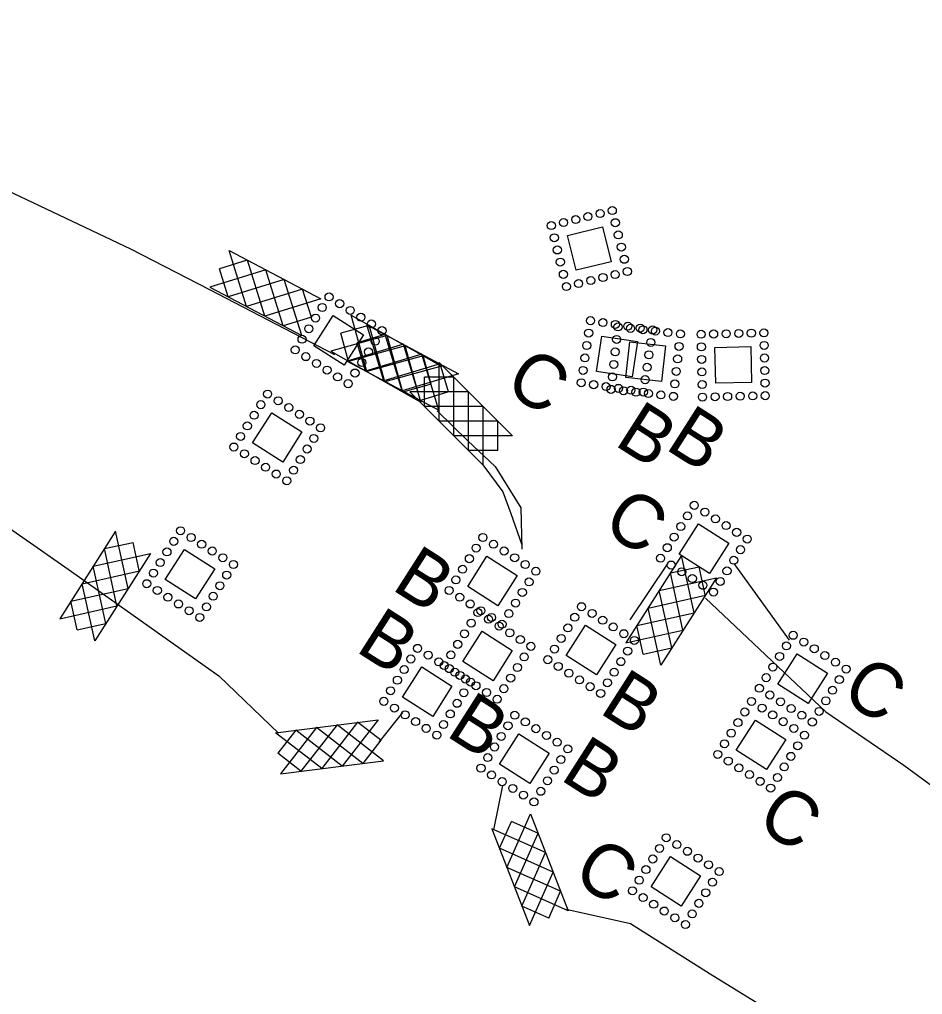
# Model space of a CAD drawing. Extents: x 2023536 to 2025544, y 819438 to 821266.
# Drawn here: x 2024579.5 to 2024831.1, y 820383.6 to 820655.3 of the extents above; entities that cross this region are included whole.
import ezdxf

# ---------------------------------------------------------------- set-up
doc = ezdxf.new("R2010")
doc.units = 0
for name, color, linetype in [('Label B Both CELL', 7, 'Continuous'), ('Label B CG CELL', 7, 'Continuous'), ('Label C Both CELL', 7, 'Continuous'), ('Label C Final CELL', 7, 'Continuous'), ('Rock Inlet Sediment Trap Type B Both CELL', 7, 'Continuous'), ('Rock Inlet Sediment Trap Type B CG CELL', 7, 'Continuous'), ('Rock Inlet Sediment Trap Type C Both CELL', 7, 'Continuous'), ('Rock Inlet Sediment Trap Type C Final CELL', 7, 'Continuous'), ('Rock Silt Check Type A Both CELL', 7, 'Continuous'), ('Rock Silt Check Type A CG CELL', 7, 'Continuous'), ('Rock Silt Check Type A Final CELL', 7, 'Continuous'), ('Temporary Silt Fence Both', 7, 'Continuous'), ('Temporary Silt Fence CG', 7, 'Continuous'), ('Temporary Silt Fence Final', 7, 'Continuous')]:
    doc.layers.add(name, color=color, linetype=linetype)

msp = doc.modelspace()

# ---------------------------------------------------------------- linework, layer by layer
at = {"layer": 'Rock Inlet Sediment Trap Type B Both CELL'}
for points in [[(2024749.55, 820565.48), (2024759.49, 820564.36), (2024758.37, 820554.43), (2024748.44, 820555.55)], [(2024773.22, 820563.91), (2024783.22, 820564.14), (2024783.45, 820554.14), (2024773.45, 820553.93)]]:
    msp.add_lwpolyline(points, close=True, dxfattribs=at)
for centre in [(2024746.24, 820569.63), (2024749.72, 820569.24), (2024753.19, 820568.85), (2024745.85, 820566.15), (2024756.67, 820568.46), (2024760.15, 820568.07), (2024763.63, 820567.68), (2024769.38, 820567.59), (2024772.88, 820567.67), (2024776.38, 820567.74), (2024779.88, 820567.82), (2024783.38, 820567.9), (2024786.88, 820567.98), (2024763.24, 820564.21), (2024769.46, 820564.09), (2024786.96, 820564.48), (2024745.46, 820562.68), (2024762.85, 820560.73), (2024787.04, 820560.98), (2024745.07, 820559.2), (2024769.54, 820560.59), (2024744.68, 820555.72), (2024762.46, 820557.25), (2024769.62, 820557.09), (2024787.12, 820557.48), (2024762.07, 820553.77), (2024769.7, 820553.59), (2024787.2, 820553.98), (2024744.29, 820552.24), (2024747.77, 820551.85), (2024751.24, 820551.46), (2024754.72, 820551.07), (2024758.2, 820550.68), (2024761.68, 820550.29), (2024769.78, 820550.09), (2024773.28, 820550.17), (2024776.78, 820550.25), (2024780.28, 820550.33), (2024783.77, 820550.41), (2024787.27, 820550.48)]:
    msp.add_circle(centre, 1.12, dxfattribs=at)
at = {"layer": 'Rock Inlet Sediment Trap Type B CG CELL'}
for points in [[(2024709.73, 820505.77), (2024718.16, 820500.4), (2024712.79, 820491.96), (2024704.36, 820497.35)], [(2024737.2, 820486.49), (2024745.63, 820481.12), (2024740.26, 820472.68), (2024731.83, 820478.07)], [(2024708.36, 820484.86), (2024716.79, 820479.48), (2024711.41, 820471.05), (2024702.99, 820476.44)], [(2024691.54, 820474.88), (2024699.98, 820469.5), (2024694.6, 820461.07), (2024686.17, 820466.45)], [(2024718.61, 820456.26), (2024727.05, 820450.88), (2024721.67, 820442.45), (2024713.24, 820447.84)]]:
    msp.add_lwpolyline(points, close=True, dxfattribs=at)
for centre in [(2024708.59, 820510.96), (2024711.54, 820509.08), (2024706.71, 820508.01), (2024714.49, 820507.2), (2024704.82, 820505.06), (2024717.44, 820505.32), (2024702.94, 820502.11), (2024720.39, 820503.44), (2024723.34, 820501.56), (2024701.06, 820499.16), (2024721.46, 820498.6), (2024699.18, 820496.2), (2024719.58, 820495.65), (2024702.13, 820494.32), (2024717.7, 820492.7), (2024705.08, 820492.44), (2024707.21, 820490.05), (2024708.03, 820490.56), (2024736.05, 820491.68), (2024710.16, 820488.17), (2024710.99, 820488.68), (2024715.82, 820489.75), (2024734.17, 820488.73), (2024739.01, 820489.8), (2024741.96, 820487.92), (2024705.33, 820487.1), (2024713.12, 820486.29), (2024713.94, 820486.8), (2024732.29, 820485.78), (2024744.91, 820486.04), (2024703.45, 820484.15), (2024716.07, 820484.4), (2024719.02, 820482.52), (2024730.41, 820482.83), (2024747.86, 820484.16), (2024750.81, 820482.27), (2024690.4, 820480.07), (2024701.57, 820481.19), (2024721.97, 820480.64), (2024728.53, 820479.87), (2024748.93, 820479.32), (2024688.52, 820477.11), (2024693.35, 820478.18), (2024699.69, 820478.24), (2024720.09, 820477.69), (2024726.65, 820476.92), (2024686.64, 820474.16), (2024696.3, 820476.3), (2024697.81, 820475.29), (2024699.25, 820474.42), (2024718.21, 820474.74), (2024729.6, 820475.04), (2024747.05, 820476.37), (2024684.76, 820471.21), (2024700.76, 820473.41), (2024702.21, 820472.54), (2024703.71, 820471.53), (2024716.33, 820471.79), (2024732.55, 820473.16), (2024735.5, 820471.28), (2024745.17, 820473.42), (2024682.87, 820468.26), (2024705.16, 820470.66), (2024706.66, 820469.65), (2024714.44, 820468.84), (2024738.45, 820469.4), (2024743.29, 820470.47), (2024703.28, 820467.71), (2024709.61, 820467.77), (2024712.56, 820465.88), (2024741.4, 820467.52), (2024680.99, 820465.31), (2024683.94, 820463.43), (2024701.39, 820464.76), (2024686.9, 820461.55), (2024699.51, 820461.8), (2024717.47, 820461.45), (2024689.85, 820459.66), (2024692.8, 820457.78), (2024697.63, 820458.85), (2024715.59, 820458.5), (2024720.42, 820459.57), (2024723.37, 820457.69), (2024695.75, 820455.9), (2024713.71, 820455.54), (2024726.32, 820455.8), (2024711.82, 820452.59), (2024729.27, 820453.92), (2024732.23, 820452.04), (2024709.94, 820449.64), (2024708.06, 820446.69), (2024730.34, 820449.09), (2024711.01, 820444.81), (2024728.46, 820446.14), (2024713.96, 820442.93), (2024726.58, 820443.19), (2024716.92, 820441.05), (2024719.87, 820439.17), (2024724.7, 820440.24), (2024722.82, 820437.28)]:
    msp.add_circle(centre, 1.12, dxfattribs=at)
at = {"layer": 'Rock Inlet Sediment Trap Type C Both CELL'}
for points in [[(2024741.74, 820567.09), (2024751.63, 820565.62), (2024750.15, 820555.73), (2024740.26, 820557.22)], [(2024768.63, 820514.73), (2024777.07, 820509.35), (2024771.69, 820500.92), (2024763.27, 820506.3)]]:
    msp.add_lwpolyline(points, close=True, dxfattribs=at)
for centre in [(2024738.58, 820571.38), (2024742.04, 820570.86), (2024745.5, 820570.34), (2024748.96, 820569.82), (2024752.42, 820569.31), (2024755.89, 820568.79), (2024738.06, 820567.92), (2024737.54, 820564.46), (2024755.37, 820565.33), (2024737.02, 820560.99), (2024754.85, 820561.86), (2024754.33, 820558.4), (2024736.51, 820557.53), (2024735.99, 820554.07), (2024739.45, 820553.55), (2024742.91, 820553.03), (2024746.37, 820552.52), (2024753.81, 820554.94), (2024749.83, 820552), (2024753.29, 820551.48), (2024767.49, 820519.92), (2024770.44, 820518.04), (2024765.61, 820516.97), (2024773.39, 820516.16), (2024763.73, 820514.02), (2024776.34, 820514.28), (2024779.3, 820512.4), (2024761.85, 820511.07), (2024782.25, 820510.52), (2024759.97, 820508.12), (2024780.37, 820507.57), (2024758.08, 820505.17), (2024778.49, 820504.61), (2024761.04, 820503.29), (2024763.99, 820501.4), (2024776.6, 820501.66), (2024766.94, 820499.52), (2024774.72, 820498.71), (2024769.89, 820497.64), (2024772.84, 820495.76)]:
    msp.add_circle(centre, 1.12, dxfattribs=at)
at = {"layer": 'Rock Inlet Sediment Trap Type C Final CELL'}
for points in [[(2024732.21, 820595.12), (2024741.92, 820597.52), (2024744.31, 820587.81), (2024734.6, 820585.43)], [(2024666.87, 820572.8), (2024675.3, 820567.43), (2024669.93, 820558.99), (2024661.5, 820564.38)], [(2024649.75, 820545.73), (2024658.18, 820540.36), (2024652.81, 820531.92), (2024644.38, 820537.31)], [(2024625.48, 820507.65), (2024633.91, 820502.27), (2024628.54, 820493.84), (2024620.11, 820499.22)], [(2024796.17, 820478.52), (2024804.6, 820473.14), (2024799.23, 820464.71), (2024790.8, 820470.09)], [(2024784.57, 820460.09), (2024793, 820454.72), (2024787.62, 820446.29), (2024779.2, 820451.67)], [(2024760.82, 820422.08), (2024769.25, 820416.71), (2024763.88, 820408.28), (2024755.45, 820413.66)]]:
    msp.add_lwpolyline(points, close=True, dxfattribs=at)
for centre in [(2024744.65, 820602.07), (2024731.06, 820598.72), (2024734.45, 820599.56), (2024737.85, 820600.4), (2024741.25, 820601.23), (2024745.49, 820598.68), (2024727.66, 820597.88), (2024728.5, 820594.48), (2024746.32, 820595.28), (2024729.33, 820591.08), (2024747.16, 820591.88), (2024748, 820588.48), (2024730.17, 820587.69), (2024748.84, 820585.08), (2024731.01, 820584.29), (2024738.65, 820582.57), (2024742.05, 820583.41), (2024745.44, 820584.24), (2024731.85, 820580.89), (2024735.25, 820581.73), (2024665.72, 820578), (2024663.84, 820575.05), (2024668.68, 820576.12), (2024671.63, 820574.24), (2024661.96, 820572.1), (2024674.58, 820572.35), (2024660.08, 820569.14), (2024677.53, 820570.47), (2024658.2, 820566.19), (2024680.48, 820568.59), (2024678.6, 820565.64), (2024656.32, 820563.24), (2024659.27, 820561.36), (2024676.72, 820562.69), (2024662.22, 820559.48), (2024674.84, 820559.74), (2024665.17, 820557.6), (2024668.12, 820555.72), (2024672.96, 820556.79), (2024671.07, 820553.83), (2024648.61, 820550.93), (2024646.73, 820547.98), (2024651.56, 820549.05), (2024654.51, 820547.17), (2024644.84, 820545.03), (2024657.46, 820545.28), (2024642.96, 820542.07), (2024660.41, 820543.4), (2024641.08, 820539.12), (2024663.36, 820541.52), (2024639.2, 820536.17), (2024661.48, 820538.57), (2024642.15, 820534.29), (2024659.6, 820535.62), (2024645.1, 820532.41), (2024657.72, 820532.67), (2024648.05, 820530.53), (2024651.01, 820528.65), (2024655.84, 820529.72), (2024653.96, 820526.76), (2024624.34, 820512.84), (2024622.45, 820509.89), (2024627.29, 820510.96), (2024630.24, 820509.08), (2024620.57, 820506.94), (2024633.19, 820507.2), (2024618.69, 820503.99), (2024636.14, 820505.32), (2024616.81, 820501.04), (2024639.09, 820503.44), (2024637.21, 820500.49), (2024614.93, 820498.09), (2024617.88, 820496.21), (2024635.33, 820497.53), (2024620.83, 820494.32), (2024633.45, 820494.58), (2024623.78, 820492.44), (2024626.73, 820490.56), (2024631.57, 820491.63), (2024629.69, 820488.68), (2024795.03, 820483.71), (2024797.98, 820481.83), (2024793.15, 820480.76), (2024800.93, 820479.95), (2024791.27, 820477.81), (2024803.88, 820478.07), (2024789.38, 820474.86), (2024806.83, 820476.19), (2024809.79, 820474.31), (2024787.5, 820471.91), (2024807.9, 820471.36), (2024785.62, 820468.96), (2024806.02, 820468.4), (2024788.57, 820467.08), (2024783.42, 820465.29), (2024786.37, 820463.41), (2024791.52, 820465.19), (2024794.48, 820463.31), (2024804.14, 820465.45), (2024781.54, 820462.34), (2024789.33, 820461.53), (2024797.43, 820461.43), (2024802.26, 820462.5), (2024779.66, 820459.39), (2024792.28, 820459.65), (2024795.23, 820457.76), (2024800.38, 820459.55), (2024777.78, 820456.44), (2024798.18, 820455.88), (2024775.9, 820453.48), (2024796.3, 820452.93), (2024774.02, 820450.53), (2024794.42, 820449.98), (2024776.97, 820448.65), (2024779.92, 820446.77), (2024792.54, 820447.03), (2024782.87, 820444.89), (2024790.66, 820444.08), (2024785.82, 820443.01), (2024788.77, 820441.13), (2024759.68, 820427.28), (2024762.63, 820425.4), (2024757.8, 820424.33), (2024765.58, 820423.52), (2024755.91, 820421.38), (2024768.53, 820421.64), (2024771.48, 820419.76), (2024754.03, 820418.43), (2024774.43, 820417.87), (2024752.15, 820415.48), (2024772.55, 820414.92), (2024750.27, 820412.52), (2024770.67, 820411.97), (2024753.22, 820410.64), (2024756.17, 820408.76), (2024768.79, 820409.02), (2024759.12, 820406.88), (2024766.91, 820406.07), (2024762.08, 820405), (2024765.03, 820403.12)]:
    msp.add_circle(centre, 1.12, dxfattribs=at)
at = {"layer": 'Rock Silt Check Type A Both CELL'}
for p, q in [((2024650.77, 820456.58), (2024679.44, 820460.18)), ((2024667.98, 820458.74), (2024657.91, 820445.84)), ((2024673.69, 820459.47), (2024663.67, 820446.56)), ((2024680.88, 820448.72), (2024667.98, 820458.74)), ((2024679.44, 820460.18), (2024669.42, 820447.28)), ((2024680.17, 820454.48), (2024673.69, 820459.47)), ((2024663.67, 820446.56), (2024650.77, 820456.58)), ((2024656.43, 820457.24), (2024651.47, 820450.87)), ((2024662.23, 820458.02), (2024652.21, 820445.12)), ((2024669.42, 820447.28), (2024656.47, 820457.3)), ((2024675.13, 820448), (2024662.23, 820458.02)), ((2024680.17, 820454.48), (2024675.13, 820448)), ((2024657.91, 820445.84), (2024651.47, 820450.87)), ((2024652.21, 820445.12), (2024680.88, 820448.72)), ((2024713.19, 820424.4), (2024716.52, 820431.86)), ((2024715.29, 820418.99), (2024721.88, 820433.93)), ((2024723.9, 820428.6), (2024716.52, 820431.86)), ((2024721.88, 820433.93), (2024732.33, 820406.98)), ((2024726.06, 820423.16), (2024711.11, 820429.76)), ((2024711.11, 820429.76), (2024721.56, 820402.81)), ((2024717.38, 820413.58), (2024723.96, 820428.57)), ((2024728.15, 820417.75), (2024713.19, 820424.4)), ((2024719.46, 820408.22), (2024726.06, 820423.16)), ((2024730.24, 820412.4), (2024715.29, 820418.99)), ((2024721.56, 820402.81), (2024728.15, 820417.75)), ((2024732.33, 820406.98), (2024717.38, 820413.58)), ((2024726.97, 820404.89), (2024730.24, 820412.4)), ((2024726.97, 820404.89), (2024719.46, 820408.22))]:
    msp.add_line(p, q, dxfattribs=at)
at = {"layer": 'Rock Silt Check Type A CG CELL'}
for p, q in [((2024671.87, 820572.92), (2024697.02, 820558.69)), ((2024676.23, 820557.18), (2024671.87, 820572.92)), ((2024676.8, 820570.07), (2024669.02, 820567.92)), ((2024681.28, 820554.33), (2024676.87, 820570.09)), ((2024681.92, 820567.24), (2024666.18, 820562.87)), ((2024671.18, 820560.04), (2024669.02, 820567.92)), ((2024686.29, 820551.5), (2024681.92, 820567.24)), ((2024666.18, 820562.87), (2024691.34, 820548.64)), ((2024686.97, 820564.38), (2024671.18, 820560.04)), ((2024691.34, 820548.64), (2024686.97, 820564.38)), ((2024691.98, 820561.56), (2024676.23, 820557.18)), ((2024694.2, 820553.68), (2024691.98, 820561.56)), ((2024696.41, 820543.39), (2024696.42, 820559.72)), ((2024696.42, 820559.72), (2024716.84, 820539.27)), ((2024697.02, 820558.69), (2024681.28, 820554.33)), ((2024694.2, 820553.68), (2024686.29, 820551.5)), ((2024692.31, 820547.49), (2024692.34, 820555.67)), ((2024700.41, 820555.65), (2024692.34, 820555.67)), ((2024700.51, 820539.28), (2024700.49, 820555.65)), ((2024704.58, 820551.55), (2024688.25, 820551.56)), ((2024688.25, 820551.56), (2024708.67, 820531.11)), ((2024704.57, 820535.21), (2024704.58, 820551.55)), ((2024708.68, 820547.44), (2024692.31, 820547.49)), ((2024708.67, 820531.11), (2024708.68, 820547.44)), ((2024712.75, 820543.38), (2024696.41, 820543.39)), ((2024712.78, 820535.2), (2024712.75, 820543.38)), ((2024716.84, 820539.27), (2024700.51, 820539.28)), ((2024712.78, 820535.2), (2024704.57, 820535.21)), ((2024763.93, 820505.94), (2024748.39, 820481.57)), ((2024767.46, 820489.99), (2024763.93, 820505.94)), ((2024760.84, 820501.09), (2024768.82, 820502.83)), ((2024770.56, 820494.95), (2024768.82, 820502.83)), ((2024757.72, 820496.2), (2024773.67, 820499.73)), ((2024773.67, 820499.73), (2024758.13, 820475.36)), ((2024764.34, 820485.1), (2024760.84, 820501.09)), ((2024754.6, 820491.31), (2024770.58, 820494.88)), ((2024761.26, 820480.25), (2024757.72, 820496.2)), ((2024758.13, 820475.36), (2024754.6, 820491.31)), ((2024751.51, 820486.46), (2024767.46, 820489.99)), ((2024753.28, 820478.44), (2024751.51, 820486.46)), ((2024748.39, 820481.57), (2024764.34, 820485.1)), ((2024753.28, 820478.44), (2024761.26, 820480.25))]:
    msp.add_line(p, q, dxfattribs=at)
at = {"layer": 'Rock Silt Check Type A Final CELL'}
for p, q in [((2024637.91, 820590.91), (2024663.48, 820577.46)), ((2024642.75, 820575.31), (2024637.91, 820590.91)), ((2024642.93, 820588.22), (2024635.22, 820585.83)), ((2024647.88, 820572.61), (2024642.99, 820588.24)), ((2024648.13, 820585.54), (2024632.53, 820580.69)), ((2024637.62, 820578.01), (2024635.22, 820585.83)), ((2024652.97, 820569.94), (2024648.13, 820585.54)), ((2024653.26, 820582.84), (2024637.62, 820578.01)), ((2024658.1, 820567.24), (2024653.26, 820582.84)), ((2024632.53, 820580.69), (2024658.1, 820567.24)), ((2024658.35, 820580.17), (2024642.75, 820575.31)), ((2024660.82, 820572.36), (2024658.35, 820580.17)), ((2024663.48, 820577.46), (2024647.88, 820572.61)), ((2024660.82, 820572.36), (2024652.97, 820569.94)), ((2024676.27, 820570.24), (2024701.75, 820556.61)), ((2024681.01, 820554.61), (2024676.27, 820570.24)), ((2024681.27, 820567.51), (2024673.55, 820565.18)), ((2024686.12, 820551.87), (2024681.34, 820567.53)), ((2024686.45, 820564.79), (2024670.82, 820560.06)), ((2024675.89, 820557.34), (2024673.55, 820565.18)), ((2024691.19, 820549.16), (2024686.45, 820564.79)), ((2024691.57, 820562.06), (2024675.89, 820557.34)), ((2024696.3, 820546.42), (2024691.57, 820562.06)), ((2024670.82, 820560.06), (2024696.3, 820546.42)), ((2024696.64, 820559.36), (2024681.01, 820554.61)), ((2024699.05, 820551.53), (2024696.64, 820559.36)), ((2024701.75, 820556.61), (2024686.12, 820551.87)), ((2024699.05, 820551.53), (2024691.19, 820549.16)), ((2024606.22, 820512.71), (2024590.69, 820488.34)), ((2024609.75, 820496.77), (2024606.22, 820512.71)), ((2024603.13, 820507.87), (2024611.12, 820509.61)), ((2024606.64, 820491.88), (2024603.13, 820507.87)), ((2024612.86, 820501.73), (2024611.12, 820509.61)), ((2024600.01, 820502.97), (2024615.96, 820506.51)), ((2024615.96, 820506.51), (2024600.43, 820482.14)), ((2024603.56, 820487.02), (2024600.01, 820502.97)), ((2024596.9, 820498.08), (2024612.87, 820501.66)), ((2024593.81, 820493.23), (2024609.75, 820496.77)), ((2024600.43, 820482.14), (2024596.9, 820498.08)), ((2024590.69, 820488.34), (2024606.64, 820491.88)), ((2024595.57, 820485.22), (2024593.81, 820493.23)), ((2024595.57, 820485.22), (2024603.56, 820487.02))]:
    msp.add_line(p, q, dxfattribs=at)
at = {"layer": 'Temporary Silt Fence Both'}
msp.add_line((2024635.05, 820472.39), (2024651.68, 820456.43), dxfattribs=at)
for points in [[(2024451.18, 820671.39), (2024467.65, 820668.95), (2024491.66, 820653.24), (2024516.25, 820637.16), (2024532.28, 820626.95), (2024574.19, 820608.57), (2024610.4, 820591.43), (2024632.45, 820580.05)], [(2024804.11, 820462.38), (2024825.87, 820447.55), (2024844.01, 820434.21), (2024867.37, 820417.27), (2024893.46, 820399.52), (2024922.15, 820379.6), (2024933.13, 820372.39), (2024970.79, 820336.3)], [(2024731.77, 820407.43), (2024749.69, 820403.39), (2024771.9, 820389.37), (2024789.09, 820378.83), (2024803.6, 820370.94)]]:
    msp.add_lwpolyline(points, dxfattribs=at)
at = {"layer": 'Temporary Silt Fence CG'}
for p, q in [((2024632.45, 820580.05), (2024667.29, 820561.94)), ((2024770.63, 820494.09), (2024804.11, 820462.38)), ((2024679.72, 820453.91), (2024686.28, 820462.2)), ((2024714.1, 820441.83), (2024711.5, 820429.46))]:
    msp.add_line(p, q, dxfattribs=at)
for points in [[(2024473.45, 820583.78), (2024493.97, 820567.43), (2024517.82, 820552.44), (2024561.2, 820524.37), (2024593.94, 820501.46), (2024635.05, 820472.39)], [(2024708.62, 820531.21), (2024714.13, 820523.7), (2024716.4, 820517.69), (2024719.46, 820508.91)]]:
    msp.add_lwpolyline(points, dxfattribs=at)
at = {"layer": 'Temporary Silt Fence Final'}
for p, q in [((2024760.14, 820503.79), (2024749.54, 820488)), ((2024778.52, 820503.69), (2024793.91, 820482.4))]:
    msp.add_line(p, q, dxfattribs=at)
msp.add_lwpolyline([(2024695.84, 820546.24), (2024704.35, 820537.94), (2024712.04, 820530.72), (2024719.18, 820519.2), (2024719.48, 820507.67)], dxfattribs=at)

# ---------------------------------------------------------------- texts
at = {"layer": 'Label B Both CELL'}
for p in [(2024744.85, 820536.95), (2024758.99, 820535.85)]:
    msp.add_text('B', height=15, rotation=327.4893, dxfattribs=at).set_placement(p)
at = {"layer": 'Label B CG CELL'}
for p in [(2024682.79, 820496.71), (2024672.75, 820479.47), (2024740.64, 820462.3), (2024697.91, 820455.93), (2024729.74, 820443.7)]:
    msp.add_text('B', height=15, rotation=327.4893, dxfattribs=at).set_placement(p)
at = {"layer": 'Label C Both CELL'}
for p in [(2024714.03, 820552.19), (2024741.31, 820513.18)]:
    msp.add_text('C', height=15, rotation=327.4893, dxfattribs=at).set_placement(p)
at = {"layer": 'Label C Final CELL'}
for p in [(2024807.81, 820466.25), (2024784.25, 820430.58), (2024732.98, 820415.72)]:
    msp.add_text('C', height=15, rotation=327.4893, dxfattribs=at).set_placement(p)

doc.saveas('drawing.dxf')
